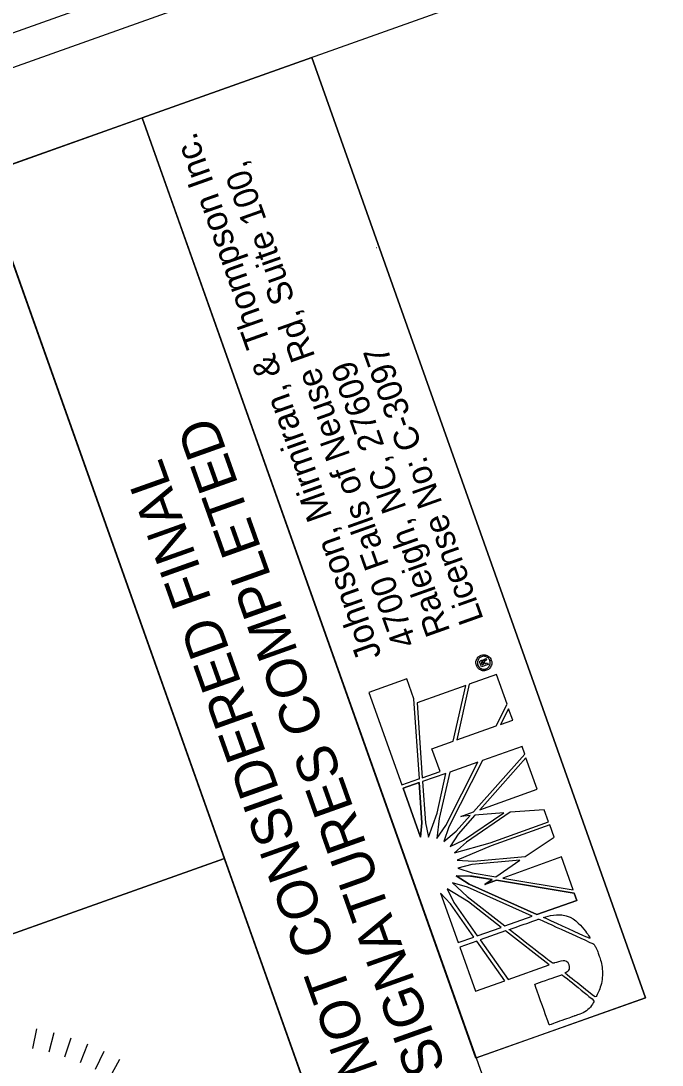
# Model space of a CAD drawing. Extents: x 1615843 to 1617444, y 901957 to 903921.
# Drawn here: x 1616019.1 to 1616107.5, y 903472.3 to 903616.2 of the extents above; entities that cross this region are included whole.
import ezdxf

# ---------------------------------------------------------------- set-up
doc = ezdxf.new("R2010")
doc.units = 0
for name, color, linetype in [('Default', 7, 'Continuous'), ('Exist Plan Preparation Drainage Flow Arrows', 7, 'Continuous'), ('Exist Plan Preparation Drainage Notes Label', 7, 'Continuous'), ('Exist Structure Minor Pipes CMP 15 Inch Text', 7, 'Continuous'), ('Exist Structure Minor Pipes RCP 15 Inch', 7, 'Continuous'), ('Prop Drainage Structure Catch Basin Grate 840 03E CELL', 7, 'Continuous'), ('Prop Plan Preparation Cover Label', 7, 'Continuous'), ('Scratch_Level_3', 7, 'Continuous')]:
    doc.layers.add(name, color=color, linetype=linetype)

msp = doc.modelspace()

# ---------------------------------------------------------------- linework, layer by layer
at = {"layer": 'Default'}
for p, q in [((1616081.91, 903527.38), (1616082.1, 903527.45)), ((1616082.1, 903527.45), (1616081.91, 903527.38)), ((1616082.46, 903527.58), (1616082.44, 903527.64)), ((1616082.46, 903527.58), (1616082.63, 903527.64)), ((1616082.63, 903527.64), (1616082.46, 903527.58)), ((1616082.59, 903527.2), (1616082.46, 903527.58)), ((1616083.52, 903527.53), (1616082.59, 903527.2)), ((1616082.62, 903527.67), (1616082.63, 903527.64)), ((1616082.63, 903527.64), (1616082.69, 903527.47)), ((1616082.69, 903527.47), (1616082.91, 903527.55)), ((1616082.85, 903527.72), (1616083.02, 903527.78)), ((1616083.02, 903527.78), (1616082.85, 903527.72)), ((1616082.85, 903527.72), (1616082.85, 903527.73)), ((1616082.91, 903527.55), (1616082.85, 903527.72)), ((1616083.02, 903527.79), (1616083.02, 903527.78)), ((1616083.02, 903527.78), (1616083.08, 903527.61)), ((1616083.08, 903527.61), (1616083.44, 903527.74)), ((1616083.44, 903527.74), (1616083.52, 903527.53)), ((1616083.75, 903528.04), (1616083.74, 903528.05)), ((1616083.75, 903528.04), (1616083.95, 903528.11)), ((1616083.95, 903528.11), (1616083.75, 903528.04)), ((1616083.94, 903528.12), (1616083.95, 903528.11)), ((1616072.31, 903525.52), (1616067.09, 903523.66)), ((1616073.28, 903522.8), (1616072.31, 903525.52)), ((1616084.66, 903526.14), (1616080.9, 903524.8)), ((1616086.12, 903522.03), (1616084.66, 903526.14)), ((1616080.43, 903524.63), (1616073.73, 903522.25)), ((1616078.68, 903516.93), (1616080.43, 903524.63)), ((1616080.9, 903524.8), (1616079.18, 903517.11)), ((1616067.09, 903523.66), (1616071.63, 903510.91)), ((1616074.04, 903511.77), (1616073.28, 903522.8)), ((1616073.73, 903522.25), (1616074.4, 903511.9)), ((1616084.61, 903519.04), (1616086.12, 903522.03)), ((1616086.34, 903521.42), (1616085.2, 903519.25)), ((1616086.9, 903519.85), (1616086.34, 903521.42)), ((1616085.2, 903519.25), (1616086.9, 903519.85)), ((1616079.18, 903517.11), (1616084.61, 903519.04)), ((1616075.77, 903515.89), (1616078.68, 903516.93)), ((1616076.88, 903512.78), (1616075.77, 903515.89)), ((1616088.19, 903516.23), (1616082.74, 903514.29)), ((1616088.57, 903515.16), (1616088.19, 903516.23)), ((1616077.69, 903505.3), (1616082.11, 903514.07)), ((1616082.74, 903514.29), (1616078.09, 903505.14)), ((1616082.11, 903514.07), (1616078.23, 903512.69)), ((1616081.51, 903507.19), (1616088.57, 903515.16)), ((1616088.72, 903514.65), (1616082.38, 903507.5)), ((1616090.26, 903510.31), (1616088.72, 903514.65)), ((1616074.44, 903511.91), (1616076.88, 903512.78)), ((1616078.23, 903512.69), (1616076.78, 903506.3)), ((1616071.63, 903510.91), (1616073.97, 903511.74)), ((1616074.01, 903511.23), (1616071.82, 903510.45)), ((1616073.97, 903511.74), (1616074.04, 903511.77)), ((1616074.38, 903505.7), (1616074.01, 903511.23)), ((1616074.4, 903511.9), (1616074.44, 903511.91)), ((1616077.69, 903512.49), (1616074.47, 903511.39)), ((1616074.47, 903511.39), (1616074.88, 903505.69)), ((1616076.49, 903507.02), (1616077.69, 903512.49)), ((1616071.82, 903510.45), (1616074.19, 903503.72)), ((1616082.38, 903507.5), (1616090.26, 903510.31)), ((1616075.31, 903503.73), (1616076.49, 903507.02)), ((1616079.74, 903506.56), (1616081.51, 903507.19)), ((1616080.14, 903503.31), (1616085.7, 903507.06)), ((1616086.57, 903507.15), (1616080.54, 903503.04)), ((1616085.7, 903507.06), (1616081.68, 903506.72)), ((1616091.26, 903507.5), (1616086.57, 903507.15)), ((1616091.86, 903505.82), (1616091.26, 903507.5)), ((1616074.19, 903503.72), (1616074.38, 903505.7)), ((1616074.88, 903505.69), (1616075.31, 903503.73)), ((1616076.78, 903506.3), (1616076.44, 903503.54)), ((1616079.1, 903504.52), (1616081.05, 903506.68)), ((1616081.68, 903506.72), (1616079.39, 903504.14)), ((1616081.05, 903506.68), (1616079.74, 903506.56)), ((1616083.78, 903502.94), (1616091.86, 903505.82)), ((1616092.02, 903505.39), (1616083.93, 903502.51)), ((1616092.61, 903503.73), (1616092.02, 903505.39)), ((1616076.44, 903503.54), (1616077.69, 903505.3)), ((1616078.09, 903505.14), (1616077.42, 903503.09)), ((1616077.42, 903503.09), (1616079.1, 903504.52)), ((1616079.39, 903504.14), (1616078.27, 903502.42)), ((1616078.27, 903502.42), (1616080.14, 903503.31)), ((1616080.54, 903503.04), (1616078.89, 903501.55)), ((1616078.89, 903501.55), (1616083.78, 903502.94)), ((1616083.93, 903502.51), (1616079.24, 903500.54)), ((1616088.64, 903501.03), (1616092.61, 903503.73)), ((1616079.24, 903500.54), (1616081.48, 903500.41)), ((1616081.26, 903499.94), (1616079.33, 903499.45)), ((1616087.87, 903500.53), (1616081.26, 903499.94)), ((1616081.48, 903500.41), (1616088.64, 903501.03)), ((1616084.58, 903498.26), (1616087.87, 903500.53)), ((1616093.61, 903501), (1616085.54, 903498.08)), ((1616095.22, 903496.47), (1616093.61, 903501)), ((1616079.1, 903498.39), (1616080.91, 903497.22)), ((1616081.3, 903498.34), (1616079.1, 903498.39)), ((1616079.33, 903499.45), (1616081.3, 903498.8)), ((1616081.3, 903498.8), (1616084.58, 903498.26)), ((1616084.07, 903497.89), (1616081.3, 903498.34)), ((1616080.67, 903496.84), (1616078.62, 903497.42)), ((1616078.62, 903497.42), (1616080.61, 903495.53)), ((1616089.6, 903492.82), (1616080.67, 903496.84)), ((1616080.91, 903497.22), (1616090.25, 903493.04)), ((1616083.07, 903497.2), (1616084.07, 903497.89)), ((1616084.67, 903497.77), (1616083.07, 903497.2)), ((1616095.39, 903496), (1616084.67, 903497.77)), ((1616085.54, 903498.08), (1616095.22, 903496.47)), ((1616078.33, 903494.53), (1616076.94, 903495.99)), ((1616076.94, 903495.99), (1616079.37, 903489.17)), ((1616080.79, 903494.81), (1616077.86, 903496.59)), ((1616077.86, 903496.59), (1616078.8, 903494.69)), ((1616080.61, 903495.53), (1616085.82, 903491.47)), ((1616095.75, 903495), (1616095.39, 903496)), ((1616081.54, 903489.94), (1616078.33, 903494.53)), ((1616078.8, 903494.69), (1616082.01, 903490.11)), ((1616085.29, 903491.28), (1616080.79, 903494.81)), ((1616090.25, 903493.04), (1616095.75, 903495)), ((1616085.82, 903491.47), (1616089.6, 903492.82)), ((1616082.01, 903490.11), (1616085.29, 903491.28)), ((1616079.37, 903489.17), (1616081.54, 903489.94)), ((1616085.92, 903490.79), (1616082.41, 903489.54)), ((1616082.41, 903489.54), (1616086.27, 903484.08)), ((1616091.92, 903486.1), (1616085.92, 903490.79)), ((1616081.97, 903489.38), (1616079.62, 903488.55)), ((1616079.62, 903488.55), (1616081.78, 903482.49)), ((1616085.81, 903483.92), (1616081.97, 903489.38)), ((1616086.27, 903484.08), (1616091.92, 903486.1)), ((1616081.78, 903482.49), (1616085.81, 903483.92))]:
    msp.add_line(p, q, dxfattribs=at)
for points in [[(1616105.21, 903481.57), (1616059.2, 903611.17), (1616035.81, 903602.86), (1616081.83, 903473.27)], [(1616074.19, 903503.72), (1616071.82, 903510.45), (1616074.01, 903511.23), (1616074.38, 903505.7)], [(1616095.75, 903495), (1616090.25, 903493.04), (1616080.91, 903497.22), (1616079.1, 903498.39), (1616080.82, 903498.4), (1616084.07, 903497.89), (1616083.07, 903497.2), (1616084.67, 903497.77), (1616095.39, 903496)]]:
    msp.add_lwpolyline(points, close=True, dxfattribs=at)
for points in [[(1616083.02, 903528.24), (1616083.07, 903528.25), (1616083.1, 903528.27), (1616083.14, 903528.29), (1616083.23, 903528.35), (1616083.3, 903528.15)], [(1616067.09, 903523.66), (1616071.63, 903510.91), (1616073.97, 903511.74), (1616074.04, 903511.77), (1616073.28, 903522.8), (1616072.31, 903525.52), (1616067.09, 903523.66)], [(1616079.18, 903517.11), (1616084.61, 903519.04), (1616086.12, 903522.03), (1616084.66, 903526.14), (1616080.9, 903524.8), (1616079.18, 903517.11), (1616079.18, 903517.11)], [(1616074.4, 903511.9), (1616074.44, 903511.91), (1616076.88, 903512.78), (1616075.77, 903515.89), (1616078.68, 903516.93), (1616080.43, 903524.63), (1616073.73, 903522.25), (1616074.4, 903511.9)], [(1616086.9, 903519.85), (1616086.9, 903519.85), (1616086.34, 903521.42), (1616085.2, 903519.25), (1616086.9, 903519.85)], [(1616077.42, 903503.09), (1616079.1, 903504.52), (1616081.05, 903506.68), (1616079.74, 903506.56), (1616081.51, 903507.19), (1616088.57, 903515.16), (1616088.19, 903516.23), (1616082.74, 903514.29), (1616078.09, 903505.14), (1616077.42, 903503.09)], [(1616076.44, 903503.54), (1616077.69, 903505.3), (1616082.11, 903514.07), (1616078.23, 903512.69), (1616076.78, 903506.3), (1616076.44, 903503.54)], [(1616090.26, 903510.31), (1616088.72, 903514.65), (1616082.38, 903507.5), (1616090.26, 903510.31)], [(1616074.38, 903505.7), (1616074.01, 903511.23), (1616071.82, 903510.45), (1616074.19, 903503.72), (1616074.38, 903505.7)], [(1616075.31, 903503.73), (1616076.49, 903507.02), (1616077.69, 903512.49), (1616074.47, 903511.39), (1616074.88, 903505.69), (1616075.31, 903503.73)], [(1616078.27, 903502.42), (1616080.14, 903503.31), (1616085.7, 903507.06), (1616081.68, 903506.72), (1616079.39, 903504.14), (1616078.27, 903502.42)], [(1616078.89, 903501.55), (1616083.78, 903502.94), (1616091.86, 903505.82), (1616091.26, 903507.5), (1616086.57, 903507.15), (1616080.54, 903503.04), (1616078.89, 903501.55)], [(1616081.48, 903500.41), (1616088.64, 903501.03), (1616092.61, 903503.73), (1616092.02, 903505.39), (1616083.93, 903502.51), (1616079.24, 903500.54), (1616081.48, 903500.41)], [(1616079.33, 903499.45), (1616081.3, 903498.8), (1616084.58, 903498.26), (1616087.87, 903500.53), (1616081.26, 903499.94), (1616079.33, 903499.45)], [(1616095.22, 903496.47), (1616093.61, 903501), (1616085.54, 903498.08), (1616095.22, 903496.47)], [(1616079.1, 903498.39), (1616080.91, 903497.22), (1616090.25, 903493.04), (1616095.75, 903495), (1616095.39, 903496), (1616084.67, 903497.77), (1616083.07, 903497.2), (1616084.07, 903497.89), (1616081.3, 903498.34), (1616079.1, 903498.39)], [(1616085.82, 903491.47), (1616089.6, 903492.82), (1616080.67, 903496.84), (1616078.62, 903497.42), (1616080.61, 903495.53), (1616085.82, 903491.47)], [(1616078.33, 903494.53), (1616076.94, 903495.99), (1616079.37, 903489.17), (1616081.54, 903489.94), (1616078.33, 903494.53)], [(1616082.01, 903490.11), (1616085.29, 903491.28), (1616080.79, 903494.81), (1616077.86, 903496.59), (1616078.8, 903494.69), (1616082.01, 903490.11)], [(1616091.92, 903486.1), (1616085.92, 903490.79), (1616082.41, 903489.54), (1616086.27, 903484.08), (1616091.92, 903486.1)], [(1616085.81, 903483.92), (1616081.97, 903489.38), (1616079.62, 903488.55), (1616081.78, 903482.49), (1616085.81, 903483.92)]]:
    msp.add_lwpolyline(points, dxfattribs=at)
for points, degree in [([(1616081.91, 903527.38), (1616081.81, 903527.67), (1616081.82, 903527.95), (1616081.94, 903528.22), (1616082.06, 903528.49), (1616082.26, 903528.68), (1616082.55, 903528.78)], 3), ([(1616083.74, 903528.05), (1616083.66, 903528.27), (1616083.52, 903528.44), (1616083.3, 903528.54), (1616083.08, 903528.65), (1616082.85, 903528.66), (1616082.62, 903528.58), (1616082.4, 903528.5), (1616082.22, 903528.34), (1616082.12, 903528.12), (1616082.03, 903527.91), (1616082.02, 903527.69), (1616082.1, 903527.45)], 3), ([(1616082.55, 903528.78), (1616082.84, 903528.88), (1616083.12, 903528.87), (1616083.39, 903528.75), (1616083.65, 903528.61), (1616083.84, 903528.4), (1616083.94, 903528.12)], 3), ([(1616083.95, 903528.11), (1616084.05, 903527.83), (1616084.03, 903527.55), (1616083.9, 903527.28), (1616083.78, 903527.01), (1616083.57, 903526.82), (1616083.29, 903526.72), (1616083, 903526.61), (1616082.72, 903526.63), (1616082.46, 903526.76), (1616082.2, 903526.9), (1616082.01, 903527.1), (1616081.91, 903527.38)], 3), ([(1616082.1, 903527.45), (1616082.18, 903527.23), (1616082.33, 903527.06), (1616082.54, 903526.95), (1616082.75, 903526.85), (1616082.99, 903526.84), (1616083.21, 903526.92), (1616083.44, 903527), (1616083.61, 903527.16), (1616083.72, 903527.37), (1616083.82, 903527.59), (1616083.83, 903527.81), (1616083.75, 903528.04)], 3), ([(1616082.44, 903527.64), (1616082.35, 903527.87), (1616082.4, 903528.02), (1616082.59, 903528.09), (1616082.67, 903528.12), (1616082.75, 903528.11), (1616082.83, 903528.05)], 3), ([(1616082.85, 903527.73), (1616082.8, 903527.86), (1616082.74, 903527.92), (1616082.66, 903527.89), (1616082.59, 903527.86), (1616082.58, 903527.79), (1616082.62, 903527.67)], 3), ([(1616082.83, 903528.05), (1616082.84, 903528.12), (1616082.91, 903528.18), (1616083.02, 903528.24)], 2), ([(1616083.3, 903528.15), (1616083.25, 903528.11), (1616083.21, 903528.08), (1616083.14, 903528.05), (1616083.06, 903528.02), (1616083.01, 903527.99), (1616082.99, 903527.96)], 3), ([(1616082.99, 903527.96), (1616082.99, 903527.93), (1616082.99, 903527.87), (1616083.02, 903527.79)], 2), ([(1616094.68, 903486.1), (1616094.81, 903485.74), (1616094.72, 903485.36), (1616094.09, 903484.99), (1616094.09, 903484.99), (1616098.34, 903481.6), (1616098.34, 903481.6), (1616099.27, 903483.44), (1616099.35, 903485.88), (1616098.7, 903487.69), (1616098.53, 903488.16), (1616098.37, 903488.51), (1616098.09, 903488.97), (1616098.09, 903488.97), (1616090.5, 903492.42), (1616090.5, 903492.42), (1616090.5, 903492.42), (1616086.42, 903490.97), (1616086.42, 903490.97), (1616086.42, 903490.97), (1616092.43, 903486.28), (1616092.43, 903486.28), (1616093.96, 903486.82), (1616094.5, 903486.6), (1616094.68, 903486.1)], 3), ([(1616094.68, 903486.1), (1616094.81, 903485.74), (1616094.72, 903485.36), (1616094.09, 903484.99), (1616094.09, 903484.99), (1616098.34, 903481.6), (1616098.34, 903481.6), (1616099.27, 903483.44), (1616099.35, 903485.88), (1616098.7, 903487.69), (1616098.53, 903488.16), (1616098.37, 903488.51), (1616098.09, 903488.97), (1616098.09, 903488.97), (1616090.5, 903492.42), (1616090.5, 903492.42), (1616090.5, 903492.42), (1616086.42, 903490.97), (1616086.42, 903490.97), (1616086.42, 903490.97), (1616092.43, 903486.28), (1616092.43, 903486.28), (1616093.96, 903486.82), (1616094.5, 903486.6), (1616094.68, 903486.1)], 3), ([(1616091.14, 903492.65), (1616091.14, 903492.65), (1616097.69, 903489.66), (1616097.69, 903489.66), (1616096.3, 903491.77), (1616093.95, 903493.53), (1616091.14, 903492.65)], 3), ([(1616089.94, 903483.43), (1616089.94, 903483.43), (1616091.94, 903477.82), (1616091.94, 903477.82), (1616091.94, 903477.82), (1616095.45, 903479.07), (1616095.45, 903479.07), (1616095.45, 903479.07), (1616095.82, 903479.2), (1616095.82, 903479.2), (1616096.92, 903479.59), (1616097.66, 903480.26), (1616098.16, 903481.16), (1616098.16, 903481.16), (1616093.72, 903484.78), (1616093.65, 903484.75), (1616093.65, 903484.75), (1616089.94, 903483.43), (1616089.94, 903483.43)], 3)]:
    msp.add_open_spline(points, degree=degree, dxfattribs=at)
at = {"layer": 'Exist Plan Preparation Drainage Flow Arrows'}
msp.add_lwpolyline([(1615865.68, 903555.66), (1616423.91, 901985.43), (1617418.05, 902338.86), (1616859.83, 903909.09)], close=True, dxfattribs=at)
at = {"layer": 'Exist Plan Preparation Drainage Notes Label'}
msp.add_lwpolyline([(1615843.02, 903552.38), (1616407.11, 901965.67), (1617443.56, 902334.13), (1616879.47, 903920.85)], close=True, dxfattribs=at)
at = {"layer": 'Exist Structure Minor Pipes CMP 15 Inch Text'}
for p, q in [((1616013.67, 903594.99), (1616035.81, 903602.86)), ((1616035.8, 903602.86), (1616102.8, 903414.38)), ((1616080.66, 903406.51), (1616013.66, 903594.99))]:
    msp.add_line(p, q, dxfattribs=at)
at = {"layer": 'Exist Structure Minor Pipes RCP 15 Inch'}
msp.add_line((1616068.12, 903584.97), (1616068.08, 903584.95), dxfattribs=at)
msp.add_line((1616068.12, 903584.97), (1616068.08, 903584.95), dxfattribs=at)
at = {"layer": 'Prop Drainage Structure Catch Basin Grate 840 03E CELL'}
for p, q in [((1616021.27, 903477.29), (1616020.71, 903474.58)), ((1616023.66, 903476.72), (1616022.93, 903474.06)), ((1616026, 903476.01), (1616025.12, 903473.39)), ((1616028.3, 903475.16), (1616027.26, 903472.6)), ((1616030.54, 903474.17), (1616029.35, 903471.68)), ((1616032.71, 903473.05), (1616031.38, 903470.63))]:
    msp.add_line(p, q, dxfattribs=at)
at = {"layer": 'Prop Plan Preparation Cover Label'}
msp.add_line((1615941.15, 903463.09), (1616047.1, 903500.76), dxfattribs=at)
for points in [[(1615872.27, 903544.74), (1616374.72, 902131.39), (1617364.06, 902483.11), (1616861.61, 903896.45)], [(1615941.15, 903463.09), (1615907.65, 903557.31), (1616013.65, 903595), (1616047.15, 903500.78)], [(1615974.66, 903368.82), (1615941.15, 903463.09), (1616047.15, 903500.78), (1616080.66, 903406.51)]]:
    msp.add_lwpolyline(points, close=True, dxfattribs=at)
at = {"layer": 'Scratch_Level_3'}
msp.add_lwpolyline([(1616081.83, 903473.26), (1616035.8, 903602.86), (1616059.2, 903611.17), (1616105.23, 903481.57)], close=True, dxfattribs=at)

# ---------------------------------------------------------------- texts
at = {"layer": 'Default'}
for s, height, p in [('Johnson, Mirmiran, & Thompson Inc.', 3.5139, (1616068.87, 903528.76)), ('4700 Falls of Neuse Rd, Suite 100, ', 3.4135, (1616073.72, 903530.49)), ('License No: C-3097', 3.4135, (1616082.92, 903533.75)), ('Raleigh, NC, 27609', 3.4135, (1616078.32, 903532.12))]:
    msp.add_text(s, height=height, rotation=109.5486, dxfattribs=at).set_placement(p)
at = {"layer": 'Exist Structure Minor Pipes CMP 15 Inch Text'}
for s, p in [('UNLESS ALL SIGNATURES COMPLETED', (1616093.34, 903427.99)), ('DOCUMENT NOT CONSIDERED FINAL', (1616083.35, 903429.82))]:
    msp.add_text(s, height=5.5, rotation=109.5707, dxfattribs=at).set_placement(p)

doc.saveas('drawing.dxf')
